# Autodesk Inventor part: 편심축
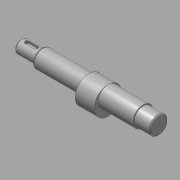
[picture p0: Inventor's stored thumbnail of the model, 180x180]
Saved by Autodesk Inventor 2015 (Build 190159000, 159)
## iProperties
Created: 2017-08
Part Number: 편심축
Material: 강철, 연강
Document SubType Name: Modeling
Designer: mduedu
Density: 1 g/cm^3
Appearance: 강철
Author: mduedu
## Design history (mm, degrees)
sketch "스케치1"
  geometry: L1 (0, 0)-(150, 0); L2 (150, 0)-(150, 8.5); L3 (150, 8.5)-(135, 8.5); L4 (135, 8.5)-(135, 9.5); L5 (135, 9.5)-(51, 9.5); L6 (51, 9.5)-(51, 8.5); L7 (51, 8.5)-(19, 8.5); L8 (19, 8.5)-(19, 6); L9 (19, 6)-(0, 6); L10 (0, 6)-(0, 0)
  constraints: 20 end point, 6 parallel, 2 collinear, 2 perpendicular, 1 horizontal
  dimensions: "d0" = 150 distance of L1.start L1.end; "d1" = 17 diameter of L3 L1; "d2" = 19 diameter of L5 L1; "d3" = 12 diameter of L9 L1; "d4" = 19 distance of L8.end L9.end; "d5" = 15 distance of L2.end L3.end; "d6" = 84 distance of L4.end L5.end
revolve "회전1" sketch "스케치1" stored, may be unused: angle "d7" = 90 deg
node "작업 평면1"
sketch "스케치2"
  geometry: C1 r 9.5 at (0, 0) reference; C2 r 13 at (0, -3.5); 1 further point
  constraints: 1 centre point, 1 tangent, 1 vertical alignment
  dimensions: "d8" = 3.5 distance of point (0, 0) C2.centre
extrude "돌출1" join sketch "스케치2" stored distance "d9" = 18; taper "d10" = 0 deg
chamfer "모따기1" distance "d11" = 1; stored, may be unused: second distance "d12" = 2, angle "d13" = 45 deg
node "작업 평면2"
sketch "스케치3"
  geometry: L1 (3.5, -2)-(-4.5, -2); L2 (-4.5, -2)-(-4.5, 2); L3 (-4.5, 2)-(3.5, 2); L4 (3.5, 2)-(3.5, -2); L5 (9.5, 6)-(9.5, -6) reference; A1 r 2 centre (3.5, 0) between (3.5, -2) and (3.5, 2); A2 r 2 centre (-4.5, 0) between (-4.5, 2) and (-4.5, -2); A3 r 2 centre (3.5, 0) between (3.5, 2) and (3.5, -2); A4 r 2 centre (-4.5, 0) between (-4.5, -2) and (-4.5, 2); 1 further point
  constraints: 8 end point, 8 point on circle, 4 centre point, 2 midpoint, 2 parallel, 1 horizontal, 1 horizontal alignment, 1 perpendicular
  dimensions: "d14" = 12 dimension on A2 A1; "d16" = 4 distance between parallel lines of L3 L1; "d17" = 4 distance edge to line of A1 L5
extrude "돌출2" cut sketch "스케치3" distance "d18" = 2.5; taper "d19" = 0 deg
chamfer "모따기2" distance "d20" = 1; stored, may be unused: second distance "d21" = 2, angle "d22" = 45 deg
chamfer "모따기3" distance "d23" = 1; stored, may be unused: second distance "d24" = 2, angle "d25" = 60 deg
fillet "모깎기1" dims "d26" = 0.5
hole "구멍1" diameter "d29" = 3.242; stored, may be unused: countersink angle "d33" = 90 deg, drill point angle "d35" = 118 deg; dims "d30" = 8, "d31" = 4, "d32" = 2, "d34" = 10, "d36" = 10, "d37" = 10
node "솔리드1"
node "절단 모서리 투영1"
other parameters: "d38" = -42
